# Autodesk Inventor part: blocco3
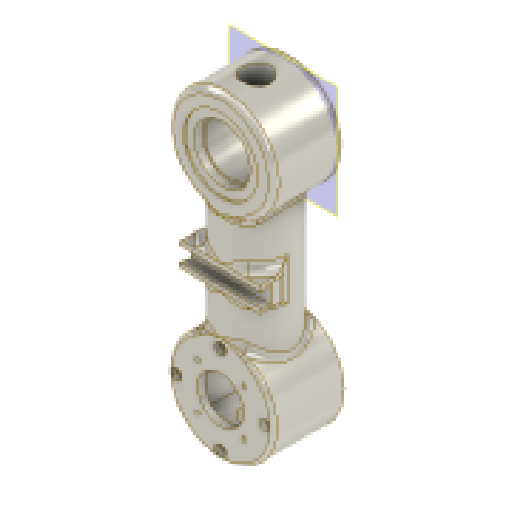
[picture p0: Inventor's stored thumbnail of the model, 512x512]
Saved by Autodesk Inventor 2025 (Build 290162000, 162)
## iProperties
Created: 2025-05
Part Number: blocco3
Material: Titanio
Document SubType Name: Modeling
Designer: 18907419
Density: 4.51 g/cm^3
Appearance: Titanio
alezza: 60,000 mm
Author: 18907419
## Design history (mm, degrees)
sketch "Schizzo1"
  geometry: C1 r 30 at (0, 0); 1 further point
  constraints: 1 centre point, 1 coincident
  dimensions: "d0" = 60 diameter of C1
extrude "Estrusione1" new body sketch "Schizzo1" stored distance "d1" = 40; taper "d2" = 0 deg
sketch "Schizzo2"
  geometry: L1 (-30, -20)-(30, -20) reference; L2 (30, 20)-(-30, 20) reference; L3 (30, -20)-(30, 20) reference; L4 (-30, -20)-(-30, 20) reference; C1 r 20 at (0, 0); 1 further point
  constraints: 1 centre point, 1 coincident
  dimensions: "d52" = 40 diameter of C1
extrude "Estrusione2" join sketch "Schizzo2" taper "d4" = 0 deg
sketch "Schizzo7"
  geometry: C1 r 8 at (0, 0); 1 further point
  constraints: 1 centre point, 1 coincident
  dimensions: "d19" = 16 diameter of C1
extrude "Estrusione7" cut sketch "Schizzo7" distance "d20" = 95.5; taper "d21" = 0 deg
sketch "Schizzo12"
  geometry: L1 (-17.5, 17.5)-(17.5, 17.5); L2 (17.5, 17.5)-(17.5, -17.5); L3 (17.5, -17.5)-(-17.5, -17.5); L4 (-17.5, -17.5)-(-17.5, 17.5); L5 (-17.5, 17.5)-(17.5, -17.5); L6 (17.5, 17.5)-(-17.5, -17.5); 1 further point
  constraints: 12 end point, 2 midpoint, 2 parallel, 1 horizontal, 1 perpendicular
  dimensions: "d38" = 35 distance of L2.end L3.end; "d39" = 35 distance of L1.end L2.end
extrude "Estrusione11" cut sketch "Schizzo12" distance "d40" = 60; taper "d41" = 0 deg
mirror "Speculare2"
sketch "Schizzo13"
  geometry: C1 r 16 at (0, 0); 1 further point
  constraints: 1 centre point
  dimensions: "d42" = 32 diameter of C1
extrude "Estrusione12" cut sketch "Schizzo13" extent not by distance; stored distance "d43" = 32; taper "d44" = 0 deg
mirror "Speculare3"
sketch "Schizzo18"
  geometry: L1 (-17.5, -17.5)-(-17.5, 17.5) reference; L2 (-17.5, 17.5)-(17.5, 17.5) reference; L3 (17.5, 17.5)-(17.5, -17.5) reference; L4 (17.5, -17.5)-(-17.5, -17.5) reference; C1 r 13 at (0, 0); C2 r 1.23 at (13.1, 13.1) reference; C3 r 1.23 at (13.1, -12.9) reference; C4 r 1.23 at (-12.9, -12.9) reference; C5 r 1.23 at (-12.9, 13.1) reference; 3 further points
  constraints: 1 centre point, 1 coincident, 1 vertical alignment
  dimensions: "d63" = 26 diameter of C1
  node "Linea chiusa proiettata5"
  node "Riferimento1"
  node "Riferimento2"
  node "Riferimento3"
  node "Riferimento4"
node "Piano di lavoro2"
extrude "Estrusione16" join sketch "Schizzo18" stored distance "d64" = 3; taper "d65" = 0 deg
sketch "Schizzo19"
  geometry: C1 r 1.7 at (0, 25) reference; 1 further point
hole "Foro3" sketch "Schizzo19" at (0, 25) diameter "d66" = 3.4; stored, may be unused: countersink angle "d70" = 90 deg, drill point angle "d72" = 118 deg; dims "d67" = 6, "d68" = 6.3, "d69" = 3.4, "d71" = 8
sketch "Schizzo20"
  geometry: C1 r 1.7 at (0, 25) reference; 2 further points
  constraints: 1 coincident
hole "Foro4" sketch "Schizzo20" at (0, 25) diameter "d76" = 3.4; stored, may be unused: countersink angle "d80" = 90 deg, drill point angle "d82" = 118 deg; dims "d77" = 6, "d78" = 6, "d79" = 3, "d81" = 8
pattern_circular "Serie circolare2" dims "d84" = 360 deg
fillet "Raccordo2" dims "d88" = 3
fillet "Raccordo3" dims "d89" = 5
fillet "Raccordo4" dims "d90" = 2
fillet "Raccordo5" dims "d91" = 2
node "Piano di lavoro3"
sketch "Schizzo23"
  geometry: L1 (0, 0)-(0, 120); L2 (20, 24.495)-(20, 95.505) reference; L3 (-23, 67)-(23, 67); L4 (23, 67)-(23, 53); L5 (23, 53)-(-23, 53); L6 (-23, 53)-(-23, 67); L7 (-23, 67)-(23, 53); L8 (23, 67)-(-23, 53); C1 r 5 at (0, 120) reference; C2 r 10.7 at (0, 0) reference; 2 further points
  constraints: 14 end point, 3 midpoint, 2 parallel, 1 horizontal, 1 perpendicular, 1 vertical
  dimensions: "d104" = 46 distance of L4.end L5.end; "d105" = 14 distance of L3.end L4.end
extrude "Estrusione19" join sketch "Schizzo23" distance "d99" = 7; taper "d101" = 0 deg; dims "d100" = 6, "d102" = 0
fillet "Raccordo6" dims "d106" = 5
fillet "Raccordo7" dims "d107" = 5
sketch "Schizzo24"
  geometry: L1 (-10.38, 0)-(-10.38, 14) reference; L2 (-10.38, 0)-(0, 0) reference; L3 (0, 14)-(0, 0) reference; L4 (-10.38, 14)-(0, 14) reference; L5 (0, 7)-(-10.38, 7); L6 (0, 11)-(-6, 12.058); L7 (-6, 12.058)-(-6, 7); L8 (0, 3)-(-6, 1.942); L9 (-6, 1.942)-(-6, 7); L10 (0, 14)-(0, 0) reference; 3 further points
  constraints: 10 end point, 3 midpoint, 2 point on line, 2 symmetric about line, 1 perpendicular
  dimensions: "d108" = 6 distance between parallel lines of L7 L3; "d109" = 80 deg angle of L7 L6; "d113" = 4 distance of point (0, 7) L6.start
extrude "Estrusione20" cut sketch "Schizzo24" extent not by distance; stored distance "d110" = 0; taper "d111" = 0 deg
fillet "Raccordo8" dims "d112" = 5
node "Piano di lavoro4"
sketch "Schizzo25"
  geometry: C1 r 14.5 at (0, 0); C2 r 16 at (0, 0) reference; 1 further point
  constraints: 1 centre point
  dimensions: "d115" = 29 diameter of C1
extrude "Estrusione21" join sketch "Schizzo25" distance "d116" = 30; taper "d117" = 0 deg
sketch "Schizzo26"
  geometry: C1 r 21 at (0, 0); 1 further point
  constraints: 1 centre point
  dimensions: "d118" = 42 diameter of C1
extrude "Estrusione22" cut sketch "Schizzo26" distance "d119" = 1; taper "d120" = 0 deg
fillet "Raccordo9" dims "d121" = 1
node "Solido1"
node "Linea chiusa proiettata1"
node "Riferimento5"
node "Riferimento6"
node "Riferimento7"
node "Linea chiusa proiettata7"
other parameters: "d92" = 13, "d114" = -4.5
